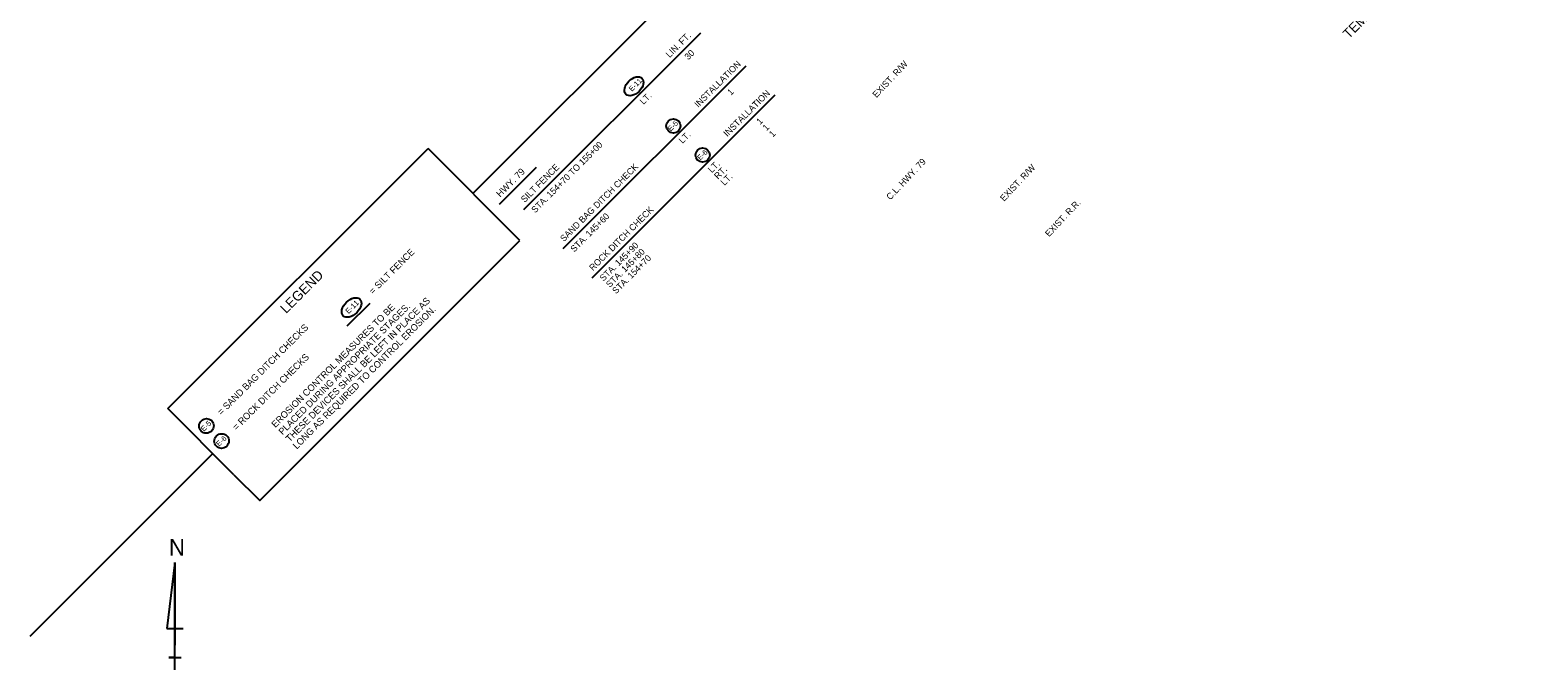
# Model space of a CAD drawing. Extents: x 1377476 to 1378879, y 1932630 to 1934097.
# Drawn here: x 1377476 to 1378879, y 1932630 to 1933226 of the extents above; entities that cross this region are included whole.
import ezdxf

# ---------------------------------------------------------------- set-up
doc = ezdxf.new("R2010")
doc.units = 0
for name, color, linetype in [('1', 7, 'Continuous'), ('44', 7, 'Continuous'), ('60', 7, 'Continuous'), ('63', 7, 'Continuous'), ('Level 1', 7, 'Continuous'), ('Level 44', 7, 'Continuous'), ('R_Draft', 7, 'Continuous')]:
    doc.layers.add(name, color=color, linetype=linetype)

msp = doc.modelspace()

# ---------------------------------------------------------------- linework, layer by layer
at = {"layer": '1'}
for p, q in [((1377887.9, 1933073.8), (1378090.3, 1933276.1)), ((1377603.7, 1932873.4), (1377846, 1933115.7)), ((1377931.6, 1933030.1), (1377846, 1933115.7)), ((1377665.3, 1932811.8), (1377603.7, 1932873.4)), ((1377475.5, 1932661.4), (1377645.6, 1932831.5))]:
    msp.add_line(p, q, dxfattribs=at)
msp.add_lwpolyline([(1377665.3, 1932811.8), (1377689.3, 1932787.8), (1377931.6, 1933030.1)], dxfattribs=at)
for centre in [(1378074.5, 1933136.7), (1378101.7, 1933109.6)]:
    msp.add_circle(centre, 6.61, dxfattribs=at)
msp.add_ellipse((1378037.8, 1933173.7), major_axis=(7.44, 7.44), ratio=0.638788, dxfattribs=at)
at = {"layer": '44'}
for p, q in [((1377935.3, 1933058.9), (1378099.9, 1933223.5)), ((1377971.8, 1933022.4), (1378142.2, 1933192.8)), ((1377999, 1932995.2), (1378169.4, 1933165.6)), ((1377912.5, 1933063.8), (1377947, 1933098.3))]:
    msp.add_line(p, q, dxfattribs=at)
at = {"layer": '63'}
for p, q in [((1377610.4, 1932730.1), (1377602.8, 1932668.5)), ((1377610.4, 1932630.1), (1377610.4, 1932730.1)), ((1377610.4, 1932730.1), (1377610.4, 1932653.1)), ((1377602.8, 1932668.5), (1377618.1, 1932668.5)), ((1377610.4, 1932630.1), (1377610.4, 1932653.1)), ((1377610.4, 1932641.6), (1377604.7, 1932641.6)), ((1377604.7, 1932641.6), (1377616.2, 1932641.6)), ((1377610.4, 1932630.1), (1377610.4, 1932641.6))]:
    msp.add_line(p, q, dxfattribs=at)
at = {"layer": 'Level 1'}
for centre, major_axis, ratio in [((1377774.8, 1932967.6), (7.75, 7.75), 0.622952), ((1377639.7, 1932857.3), (-4.87, -4.86), 0.97521), ((1377653.8, 1932843.2), (-4.87, -4.86), 0.97521)]:
    msp.add_ellipse(centre, major_axis=major_axis, ratio=ratio, dxfattribs=at)
at = {"layer": 'Level 44'}
msp.add_lwpolyline([(1377770.8, 1932950.4), (1377792.1, 1932971.7)], dxfattribs=at)

# ---------------------------------------------------------------- texts
at = {"layer": '1'}
for s, p in [('E-11', (1378035.8, 1933168.4)), ('E-5 ', (1378072.1, 1933131.4)), ('E-6 ', (1378099.5, 1933104.4))]:
    msp.add_text(s, height=4.8, rotation=45, dxfattribs=at).set_placement(p)
at = {"layer": '44'}
for s, height, p in [('LIN. FT.', 6, (1378071, 1933199.9)), ('30', 6, (1378088.4, 1933197.8)), ('INSTALLATION', 6, (1378097.6, 1933153.5)), ('LT.', 6, (1378046.6, 1933156.2)), ('INSTALLATION', 6, (1378124.7, 1933126.3)), ('1', 6, (1378128.2, 1933164.7)), ('1', 6, (1378155.3, 1933137.5)), ('LT.', 6, (1378083, 1933119.8)), ('1', 6, (1378161.2, 1933131.7)), ('1', 6, (1378167.1, 1933125.8)), ('STA. 154+70 TO 155+00', 6, (1377945.8, 1933055.2)), ('SILT FENCE      ', 6, (1377936, 1933064.9)), ('SAND BAG DITCH CHECK', 6, (1377972.6, 1933028.4)), ('LT.', 6, (1378110.2, 1933092.6)), ('HWY. 79', 6.25, (1377913.2, 1933069.9)), ('RT.', 6, (1378116, 1933086.6)), ('LT.', 6, (1378122, 1933080.8)), ('ROCK DITCH CHECK', 6, (1377999.7, 1933001.3)), ('STA. 145+60', 6, (1377982.2, 1933018.7)), ('STA. 145+90', 6, (1378009.4, 1932991.6)), ('STA. 145+80', 6, (1378015.3, 1932985.7)), ('STA. 154+70', 6, (1378021.1, 1932979.8))]:
    msp.add_text(s, height=height, rotation=45, dxfattribs=at).set_placement(p)
at = {"layer": '60'}
msp.add_text('TEMPORARY EROSION CONTROL DETAILS', height=9, rotation=45, dxfattribs=at).set_placement((1378703.4, 1933217.4))
at = {"layer": '63'}
msp.add_text('N', height=15.4, rotation=360, dxfattribs=at).set_placement((1377604.8, 1932736.5))
at = {"layer": 'Level 1'}
for s, height, p in [('= SILT FENCE', 6.25, (1377794.8, 1932979.4)), ('THESE DEVICES SHALL BE LEFT IN PLACE AS ', 6.25, (1377717.2, 1932841.9)), ('EROSION CONTROL MEASURES TO BE', 6.25, (1377703.9, 1932855.2)), ('PLACED DURING APPROPRIATE STAGES. ', 6.25, (1377710.5, 1932848.5)), ('LONG AS REQUIRED TO CONTROL EROSION.', 6.25, (1377723.8, 1932835.2)), ('E-11 ', 4.88, (1377772, 1932961.4)), ('= SAND BAG DITCH CHECKS', 6.25, (1377653.6, 1932866.8)), ('= ROCK DITCH CHECKS', 6.25, (1377667.7, 1932852.7)), ('E-5 ', 4.88, (1377637.3, 1932851.8)), ('E-6 ', 4.88, (1377651.5, 1932837.8))]:
    msp.add_text(s, height=height, rotation=45, dxfattribs=at).set_placement(p)
at = {"layer": 'Level 44'}
msp.add_text('LEGEND', height=9.14, rotation=45, dxfattribs=at).set_placement((1377713.9, 1932961.4))
at = {"layer": 'R_Draft'}
for s, p in [('EXIST. R/W', (1378263.6, 1933162.5)), ('C.L. HWY. 79', (1378276.5, 1933067.3)), ('EXIST. R/W', (1378382.4, 1933066)), ('EXIST. R.R.', (1378424.3, 1933033))]:
    msp.add_text(s, height=6, rotation=46.6607, dxfattribs=at).set_placement(p)

doc.saveas('drawing.dxf')
